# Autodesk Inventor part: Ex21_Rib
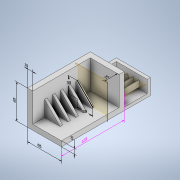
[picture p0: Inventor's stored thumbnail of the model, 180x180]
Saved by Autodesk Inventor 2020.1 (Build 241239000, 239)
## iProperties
Created: 2019-11
Part Number: Ex21_Rib
Material: Generic
Document SubType Name: Modeling
Designer: Synergysoft Dell02
Density: 1 g/cm^3
Appearance: Default
Author: Synergysoft Dell02
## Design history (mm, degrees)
node "Annotations"
  node "Linear Dimension 1" dims "d0" = 65, "d1" = 10, "d39" = 65, "d40" = 10, "d43" = 65 (derived)
  node "Linear Dimension 2" dims "d0" = 65, "d1" = 10, "d39" = 65, "d40" = 10, "d46" = 65 (derived)
  node "Linear Dimension 3" dims "d0" = 65, "d1" = 10, "d39" = 65, "d40" = 10, "d49" = 10 (derived)
  node "Linear Dimension 4" dims "d0" = 65, "d1" = 10, "d39" = 65, "d40" = 10, "d52" = 10 (derived)
  node "Linear Dimension 5" dims "d0" = 65, "d1" = 10, "d39" = 65, "d40" = 10, "d53" = 120 (derived)
  node "Linear Dimension 6" dims "d0" = 65, "d1" = 10, "d39" = 65, "d40" = 10, "d56" = 25 (derived)
sketch "Sketch1"
  geometry: L1 (0, 0)-(0, 65); L2 (0, 65)-(10, 65); L3 (10, 65)-(10, 10); L4 (10, 10)-(65, 10); L5 (65, 10)-(65, 0); L6 (65, 0)-(0, 0); L7 (10, 65)-(65, 65); L8 (65, 65)-(65, 10)
  constraints: 16 end point, 5 perpendicular, 1 collinear, 1 horizontal, 1 vertical
  dimensions: "d0" = 65 distance of L1.start L1.end; "d1" = 10 distance of L1.end L2.end; "d39" = 65 distance between parallel lines of L5 L1; "d40" = 10 distance of L4.end L5.end
extrude "Extrusion1" new body sketch "Sketch1" distance "d5" = 120; taper "d6" = 0 deg
extrude "Extrusion2" join sketch "Sketch1" distance "d7" = 10 (= d1); taper "d8" = 0 deg
workplane "Work Plane4"
  workplane "Work Plane3"
sketch "Sketch2"
  geometry: L1 (10, 40)-(40, 10); L2 (65, 10)-(10, 10) reference; L3 (10, 10)-(10, 65) reference; 1 further point
  constraints: 2 end point, 2 point on line
  dimensions: "d12" = 30 distance from line of L2 L1.start; "d13" = 30 distance from line of L1.end L3
feature "Rib1" sketch "Sketch2" dims "d14" = 5, "d15" = 5, "d16" = 0, "d17" = 0, "d18" = 1, "d19" = 1
sketch "Sketch6"
  geometry: L1 (-65, 10)-(-65, 65) reference; L2 (-65, 30)-(0, 30); L3 (0, 30)-(0, 0); L4 (0, 0)-(-65, 0); L5 (-65, 0)-(-65, 30); 1 further point
  constraints: 8 end point, 2 parallel, 1 horizontal, 1 perpendicular, 1 point on line
  dimensions: "d57" = 30 distance between parallel lines of L4 L2
extrude "Extrusion3" join sketch "Sketch6" distance "d58" = 50; taper "d59" = 0 deg
shell "Shell1" dims "d60" = 10, "d61" = 6
workplane "Work Plane5"
sketch "Sketch7"
  geometry: L1 (-2, 11)-(53, 11); L2 (59, 0)-(-6, 0) reference; L3 (-2, 22)-(53, 22); L4 (-2, 33)-(53, 33); L5 (53, 44)-(53, 0) reference; L6 (-1.5, 46)-(53.5, 46); L7 (10, 0)-(10, 44); L8 (0, 0)-(0, 44) reference; L9 (21, 0)-(21, 44); L10 (32, 0)-(32, 44); L11 (43, 0)-(43, 44); L12 (53, 44)-(53, 0) reference; L13 (53, 44)-(53, 0) reference
  constraints: 16 end point, 8 parallel, 3 point on line, 1 horizontal, 1 midpoint, 1 vertical
  dimensions: "d63" = 55 distance of L1.start L1.end; "d64" = 11 distance between parallel lines of L1 L2; "d65" = 11 distance between parallel lines of L1 L3 (= d64); "d66" = 11 distance between parallel lines of L3 L4 (= d64); "d68" = 44 distance of L7.start L7.end; "d69" = 10 distance between parallel lines of L7 L8; "d70" = 11 distance between parallel lines of L7 L9; "d71" = 11 distance between parallel lines of L9 L10; "d72" = 11 distance between parallel lines of L10 L11
  node "Projected Loop1"
sketch "Sketch8"
  geometry: L1 (0, 24)-(44, 24) reference; L2 (0, 24)-(0, 0) reference; L3 (0, 0)-(44, 0) reference; L4 (44, 0)-(44, 24) reference; 1 further point
extrude "Extrusion4" cut sketch "Sketch8" distance "d73" = 10; taper "d74" = 0 deg
feature "Rib5" dims "d75" = 1, "d76" = 10, "d77" = 10 deg, "d78" = 0, "d79" = 1, "d80" = 1
pattern_linear "Rectangular Pattern1" dims "d83" = 15
sketch "Sketch3"
  geometry: L1 (10, 40)-(40, 10) reference; 1 further point
feature "Rib2" sketch "Sketch3" dims "d20" = 5, "d21" = 5, "d22" = 0, "d23" = 0, "d24" = 1, "d25" = 1
sketch "Sketch4"
  geometry: L1 (10, 40)-(40, 10) reference; 1 further point
feature "Rib3" sketch "Sketch4" dims "d26" = 5, "d27" = 5, "d28" = 0, "d29" = 0, "d30" = 1, "d31" = 1
sketch "Sketch5"
  geometry: L1 (10, 40)-(40, 10) reference; 1 further point
feature "Rib4" sketch "Sketch5" dims "d33" = 5, "d34" = 5, "d35" = 0, "d36" = 0, "d37" = 1, "d38" = 1
body "Solid1"
workplane "Work Plane1"
workplane "Work Plane2"
node "Projected Loop2"
other parameters: "d9" = 25, "d10" = 25, "d11" = 25, "d32" = 25, "d62" = 15, "d41" = 0 (derived), "d44" = 0 (derived), "d47" = 0 (derived), "d50" = 0 (derived), "d54" = 67.75 (derived), "d55" = 22.13259 (derived)
